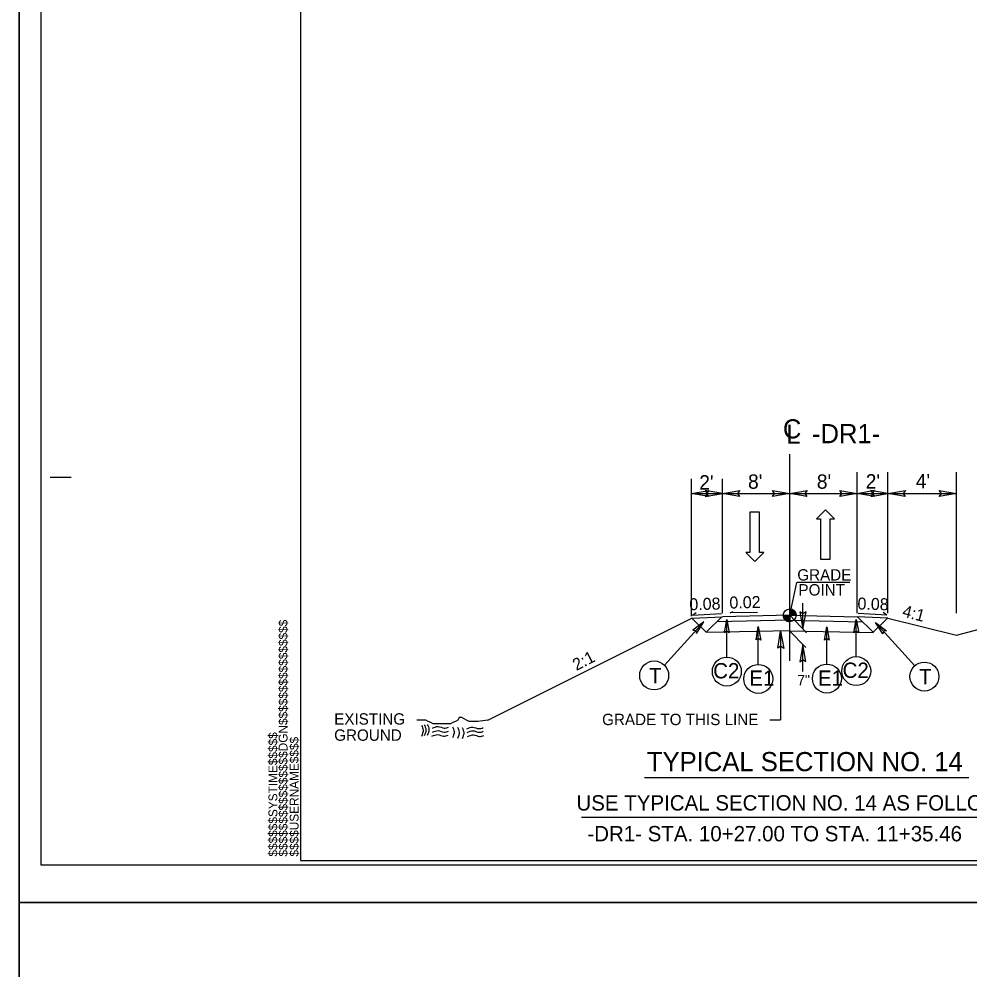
# Model space of a CAD drawing. Extents: x 573813 to 575363, y -54752 to -53123.
# Drawn here: x 574669.7 to 574782.7, y -54231.4 to -54118.5 of the extents above; entities that cross this region are included whole.
import ezdxf

# ---------------------------------------------------------------- set-up
doc = ezdxf.new("R2010")
doc.units = 0
for name, color, linetype in [('Old_Level_1', 7, 'Continuous'), ('Old_Level_11', 7, 'Continuous'), ('Old_Level_2', 7, 'Continuous'), ('Old_Level_3', 7, 'Continuous'), ('Prop Lane Arrow CELL', 7, 'Continuous'), ('Prop Pavement Schedule Description CELL', 7, 'Continuous'), ('Sheet Cutting Line CELL', 7, 'Continuous'), ('Sheet Plot Border Inside CELL', 7, 'Continuous'), ('Sheet Plot Border Outside CELL', 7, 'Continuous'), ('Sheet Typical CELL', 7, 'Continuous'), ('Typical Grade Point Symbol CELL', 7, 'Continuous'), ('Typical ID Circle CELL', 7, 'Continuous'), ('Typical Terminator CELL', 7, 'Continuous'), ('Typical Text ID Circle CELL', 7, 'Continuous'), ('Typical Text Label CELL', 7, 'Continuous')]:
    doc.layers.add(name, color=color, linetype=linetype)

msp = doc.modelspace()

# ---------------------------------------------------------------- linework, layer by layer
at = {"layer": 'Old_Level_1'}
for p, q in [((574781.07, -54191.67), (574799.55, -54186.73)), ((574749.71, -54189.27), (574750.16, -54188.98)), ((574754.17, -54189.02), (574754.54, -54188.83)), ((574757.43, -54188.95), (574754.17, -54189.02)), ((574772.81, -54189.27), (574772.36, -54188.98)), ((574725.4, -54201.75), (574749.64, -54189.63)), ((574749.64, -54189.63), (574753.26, -54189.46)), ((574749.64, -54189.63), (574751.34, -54191.32)), ((574749.71, -54189.27), (574753.14, -54189.1)), ((574753.2, -54189.46), (574751.34, -54191.32)), ((574761.26, -54189.89), (574752.59, -54190.07)), ((574761.26, -54189.3), (574753.26, -54189.46)), ((574761.26, -54189.3), (574769.26, -54189.46)), ((574761.26, -54189.89), (574769.93, -54190.07)), ((574772.93, -54189.63), (574769.26, -54189.46)), ((574769.32, -54189.46), (574771.17, -54191.32)), ((574772.81, -54189.27), (574769.38, -54189.1)), ((574772.87, -54189.63), (574771.18, -54191.32)), ((574772.93, -54189.63), (574781.07, -54191.67)), ((574761.28, -54191.15), (574751.33, -54191.33)), ((574761.24, -54191.15), (574771.19, -54191.33))]:
    msp.add_line(p, q, dxfattribs=at)
msp.add_lwpolyline([(574725.4, -54201.75), (574724.22, -54201.9), (574723.93, -54201.9), (574723.48, -54201.9), (574723.19, -54201.9), (574722.89, -54201.75), (574722.6, -54201.6), (574722.3, -54201.45), (574722.01, -54201.45), (574721.86, -54201.75), (574721.57, -54201.9), (574721.27, -54202.04), (574720.98, -54202.19), (574720.68, -54202.19), (574720.39, -54202.19), (574720.09, -54202.19), (574719.8, -54202.19), (574719.5, -54202.19), (574719.21, -54202.19), (574718.91, -54202.19), (574718.62, -54202.04), (574718.32, -54201.9), (574718.03, -54201.75), (574717.58, -54201.75), (574717.29, -54201.75), (574716.99, -54201.75)], dxfattribs=at)
at = {"layer": 'Old_Level_11'}
for p, q in [((574749.59, -54189.42), (574749.59, -54173.08)), ((574753.26, -54189.06), (574753.26, -54173.08)), ((574769.26, -54189.06), (574769.26, -54172.29)), ((574772.93, -54189.06), (574772.93, -54172.29)), ((574781.07, -54189.06), (574781.07, -54172.29)), ((574749.59, -54174.83), (574753.26, -54174.83)), ((574753.26, -54174.82), (574761.26, -54174.82)), ((574761.26, -54174.82), (574769.26, -54174.82)), ((574769.26, -54174.82), (574772.93, -54174.82)), ((574772.93, -54174.82), (574781.07, -54174.82)), ((574761.26, -54189.3), (574762.11, -54185.42)), ((574768.38, -54185.42), (574762.11, -54185.42)), ((574762.83, -54190.93), (574762.83, -54187.85)), ((574746.38, -54195.23), (574751.04, -54190.09)), ((574761.26, -54189.3), (574763.25, -54191.36)), ((574760.18, -54191.17), (574760.18, -54201.7)), ((574761.25, -54191.13), (574763.19, -54193.13)), ((574776.12, -54195.28), (574771.45, -54190.14)), ((574762.83, -54195.97), (574762.83, -54192.76)), ((574758.9, -54201.7), (574760.18, -54201.7)), ((574736.55, -54213.27), (574788.44, -54213.27))]:
    msp.add_line(p, q, dxfattribs=at)
for points in [[(574751.63, -54175.18), (574749.59, -54174.83), (574751.65, -54174.46), (574751.38, -54174.83)], [(574751.21, -54175.18), (574753.26, -54174.83), (574751.2, -54174.47), (574751.46, -54174.83)], [(574755.31, -54175.17), (574753.26, -54174.82), (574755.32, -54174.46), (574755.06, -54174.82)], [(574759.21, -54174.47), (574761.26, -54174.82), (574759.2, -54175.18), (574759.46, -54174.82)], [(574763.31, -54175.17), (574761.26, -54174.82), (574763.32, -54174.46), (574763.06, -54174.82)], [(574767.21, -54174.47), (574769.26, -54174.82), (574767.2, -54175.18), (574767.46, -54174.82)], [(574771.31, -54175.17), (574769.26, -54174.82), (574771.32, -54174.45), (574771.06, -54174.82)], [(574770.88, -54175.17), (574772.93, -54174.82), (574770.87, -54174.46), (574771.13, -54174.82)], [(574774.98, -54175.17), (574772.93, -54174.82), (574774.99, -54174.46), (574774.73, -54174.82)], [(574779.02, -54174.47), (574781.07, -54174.82), (574779.01, -54175.18), (574779.27, -54174.82)], [(574762.48, -54188.88), (574762.83, -54190.93), (574763.2, -54188.87), (574762.83, -54189.13)], [(574759.83, -54193.22), (574760.18, -54191.17), (574760.55, -54193.23), (574760.18, -54192.97)], [(574763.18, -54194.8), (574762.83, -54192.76), (574762.46, -54194.81), (574762.83, -54194.55)]]:
    msp.add_lwpolyline(points, close=True, dxfattribs=at)
at = {"layer": 'Old_Level_2'}
msp.add_line((574761.26, -54194.72), (574761.26, -54170.16), dxfattribs=at)
for points in [[(574717.53, -54202.37), (574717.72, -54202.93), (574717.52, -54203.68)], [(574717.53, -54202.37), (574717.72, -54202.93), (574717.52, -54203.68)], [(574717.86, -54202.3), (574718.05, -54202.87), (574717.85, -54203.62)], [(574717.86, -54202.3), (574718.05, -54202.87), (574717.85, -54203.62)], [(574718.22, -54202.26), (574718.41, -54202.83), (574718.2, -54203.58)], [(574718.22, -54202.26), (574718.41, -54202.83), (574718.2, -54203.58)], [(574718.82, -54202.71), (574719.5, -54202.51), (574720.23, -54202.69), (574720.75, -54202.58)], [(574718.82, -54202.71), (574719.5, -54202.51), (574720.23, -54202.69), (574720.75, -54202.58)], [(574718.77, -54203.66), (574719.45, -54203.47), (574720.17, -54203.65), (574720.7, -54203.53)], [(574718.77, -54203.66), (574719.45, -54203.47), (574720.17, -54203.65), (574720.7, -54203.53)], [(574718.82, -54203.18), (574719.5, -54202.99), (574720.22, -54203.17), (574720.74, -54203.05)], [(574718.82, -54203.18), (574719.5, -54202.99), (574720.22, -54203.17), (574720.74, -54203.05)], [(574721.21, -54202.54), (574721.4, -54203.11), (574721.2, -54203.86)], [(574721.21, -54202.54), (574721.4, -54203.11), (574721.2, -54203.86)], [(574721.81, -54202.59), (574722, -54203.16), (574721.8, -54203.91)], [(574721.81, -54202.59), (574722, -54203.16), (574721.8, -54203.91)], [(574722.36, -54202.64), (574722.55, -54203.21), (574722.35, -54203.95)], [(574722.36, -54202.64), (574722.55, -54203.21), (574722.35, -54203.95)], [(574722.93, -54202.77), (574723.61, -54202.57), (574724.33, -54202.76), (574724.86, -54202.64)], [(574722.93, -54202.77), (574723.61, -54202.57), (574724.33, -54202.76), (574724.86, -54202.64)], [(574722.95, -54203.2), (574723.63, -54203), (574724.35, -54203.19), (574724.87, -54203.07)], [(574722.95, -54203.2), (574723.63, -54203), (574724.35, -54203.19), (574724.87, -54203.07)], [(574723.01, -54203.7), (574723.7, -54203.5), (574724.42, -54203.68), (574724.94, -54203.57)], [(574723.01, -54203.7), (574723.7, -54203.5), (574724.42, -54203.68), (574724.94, -54203.57)]]:
    msp.add_spline(points, degree=3, dxfattribs=at)
at = {"layer": 'Prop Lane Arrow CELL'}
for p, q in [((574756.54, -54177.05), (574756.54, -54181.82)), ((574757.66, -54177.05), (574756.54, -54177.05)), ((574757.66, -54181.82), (574757.66, -54177.05)), ((574765.51, -54176.78), (574764.42, -54177.85)), ((574766.56, -54177.85), (574765.51, -54176.78)), ((574764.42, -54177.85), (574764.93, -54177.85)), ((574764.93, -54177.85), (574764.93, -54182.63)), ((574766.05, -54182.63), (574766.05, -54177.85)), ((574766.05, -54177.85), (574766.56, -54177.85)), ((574756.54, -54181.82), (574756.03, -54181.82)), ((574756.03, -54181.82), (574757.12, -54182.9)), ((574757.12, -54182.9), (574758.17, -54181.82)), ((574758.17, -54181.82), (574757.66, -54181.82)), ((574764.93, -54182.63), (574766.05, -54182.63))]:
    msp.add_line(p, q, dxfattribs=at)
at = {"layer": 'Sheet Cutting Line CELL'}
for p, q in [((574669.73, -54223.42), (574669.73, -54003.31)), ((575006.71, -54223.42), (574669.73, -54223.42)), ((574669.73, -54443.54), (574669.73, -54223.42)), ((574669.73, -54223.42), (575006.71, -54223.42))]:
    msp.add_line(p, q, dxfattribs=at)
at = {"layer": 'Sheet Plot Border Inside CELL'}
msp.add_lwpolyline([(575005.81, -54007.8), (574672.33, -54007.8), (574672.33, -54218.93), (575005.81, -54218.93)], close=True, dxfattribs=at)
at = {"layer": 'Sheet Plot Border Outside CELL'}
for p, q in [((574669.73, -54003.31), (574669.73, -54223.42)), ((574669.73, -54223.42), (575006.71, -54223.42)), ((575006.71, -54223.42), (574669.73, -54223.42)), ((574669.73, -54223.42), (574669.73, -54443.54))]:
    msp.add_line(p, q, dxfattribs=at)
msp.add_lwpolyline([(575006.71, -54003.31), (574669.73, -54003.31), (574669.73, -54223.42), (575006.71, -54223.42)], close=True, dxfattribs=at)
at = {"layer": 'Sheet Typical CELL'}
for p, q in [((574673.43, -54172.9), (574675.93, -54172.9)), ((574703.15, -54218.42), (574703.15, -54218.42)), ((574703.15, -54218.42), (574703.15, -54218.42)), ((574703.15, -54218.42), (574703.15, -54218.42)), ((574703.15, -54218.42), (574703.15, -54218.42)), ((574703.15, -54218.42), (574703.15, -54218.42)), ((574703.15, -54218.42), (574703.15, -54218.42))]:
    msp.add_line(p, q, dxfattribs=at)
msp.add_lwpolyline([(575003.31, -54008.31), (574703.15, -54008.31), (574703.15, -54218.42), (575003.31, -54218.42)], close=True, dxfattribs=at)
msp.add_lwpolyline([(574710.65, -54218.42), (574710.65, -54218.42)], dxfattribs=at)
at = {"layer": 'Typical Grade Point Symbol CELL'}
for p, q in [((574761.26, -54189.3), (574761.26, -54188.53)), ((574760.5, -54189.3), (574761.26, -54189.3)), ((574762.02, -54189.3), (574761.26, -54189.3)), ((574761.26, -54190.06), (574761.26, -54189.3)), ((574761.26, -54189.3), (574761.26, -54190.06))]:
    msp.add_line(p, q, dxfattribs=at)
for points in [[(574761.27, -54188.53), (574761.27, -54188.53), (574761.27, -54189.3)], [(574761.28, -54188.53), (574761.28, -54189.3)], [(574761.3, -54188.53), (574761.3, -54189.3)], [(574761.31, -54188.53), (574761.31, -54189.3)], [(574761.33, -54188.54), (574761.33, -54189.3)], [(574761.34, -54188.54), (574761.34, -54189.3)], [(574761.36, -54188.54), (574761.36, -54189.3)], [(574761.37, -54188.54), (574761.37, -54189.3)], [(574761.39, -54188.54), (574761.39, -54189.3)], [(574761.4, -54188.55), (574761.4, -54189.3)], [(574761.42, -54188.55), (574761.42, -54189.3)], [(574761.43, -54188.55), (574761.43, -54189.3)], [(574761.45, -54188.56), (574761.45, -54189.3)], [(574761.46, -54188.56), (574761.46, -54189.3)], [(574761.48, -54188.56), (574761.48, -54189.3)], [(574761.49, -54188.57), (574761.49, -54189.3)], [(574761.51, -54188.57), (574761.51, -54189.3)], [(574761.53, -54188.58), (574761.53, -54189.3)], [(574761.54, -54188.59), (574761.54, -54189.3)], [(574761.56, -54188.59), (574761.56, -54189.3)], [(574761.57, -54188.6), (574761.57, -54189.3)], [(574761.59, -54188.61), (574761.59, -54189.3)], [(574761.6, -54188.61), (574761.6, -54189.3)], [(574761.62, -54188.62), (574761.62, -54189.3)], [(574761.63, -54188.63), (574761.63, -54189.3)], [(574761.65, -54188.64), (574761.65, -54189.3)], [(574761.66, -54188.65), (574761.66, -54189.3)], [(574761.68, -54188.66), (574761.68, -54189.3)], [(574761.69, -54188.67), (574761.69, -54189.3)], [(574761.71, -54188.68), (574761.71, -54189.3)], [(574761.72, -54188.69), (574761.72, -54189.3)], [(574761.74, -54188.7), (574761.74, -54189.3)], [(574761.75, -54188.72), (574761.75, -54189.3)], [(574761.77, -54188.73), (574761.77, -54189.3)], [(574761.78, -54188.74), (574761.78, -54189.3)], [(574761.8, -54188.76), (574761.8, -54189.3)], [(574761.82, -54188.77), (574761.82, -54189.3)], [(574761.83, -54188.79), (574761.83, -54189.3)], [(574761.85, -54188.81), (574761.85, -54189.3)], [(574761.86, -54188.83), (574761.86, -54189.3)], [(574761.88, -54188.85), (574761.88, -54189.3)], [(574761.89, -54188.87), (574761.89, -54189.3)], [(574761.91, -54188.89), (574761.91, -54189.3)], [(574761.92, -54188.92), (574761.92, -54189.3)], [(574761.94, -54188.95), (574761.94, -54189.3)], [(574761.95, -54188.98), (574761.95, -54189.3)], [(574760.5, -54189.3), (574760.5, -54189.38)], [(574760.51, -54189.3), (574760.51, -54189.47)], [(574760.53, -54189.3), (574760.53, -54189.52)], [(574760.54, -54189.3), (574760.54, -54189.57)], [(574760.56, -54189.3), (574760.56, -54189.6)], [(574760.58, -54189.3), (574760.58, -54189.64)], [(574760.59, -54189.3), (574760.59, -54189.67)], [(574760.61, -54189.3), (574760.61, -54189.69)], [(574760.62, -54189.3), (574760.62, -54189.72)], [(574760.64, -54189.3), (574760.64, -54189.74)], [(574760.65, -54189.3), (574760.65, -54189.76)], [(574760.67, -54189.3), (574760.67, -54189.78)], [(574760.68, -54189.3), (574760.68, -54189.8)], [(574760.7, -54189.3), (574760.7, -54189.81)], [(574760.71, -54189.3), (574760.71, -54189.83)], [(574760.73, -54189.3), (574760.73, -54189.85)], [(574760.74, -54189.3), (574760.74, -54189.86)], [(574760.76, -54189.3), (574760.76, -54189.87)], [(574760.77, -54189.3), (574760.77, -54189.89)], [(574760.79, -54189.3), (574760.79, -54189.9)], [(574760.8, -54189.3), (574760.8, -54189.91)], [(574760.82, -54189.3), (574760.82, -54189.92)], [(574760.83, -54189.3), (574760.83, -54189.93)], [(574760.85, -54189.3), (574760.85, -54189.94)], [(574760.87, -54189.3), (574760.87, -54189.95)], [(574760.88, -54189.3), (574760.88, -54189.96)], [(574760.9, -54189.3), (574760.9, -54189.97)], [(574760.91, -54189.3), (574760.91, -54189.98)], [(574760.93, -54189.3), (574760.93, -54189.98)], [(574760.94, -54189.3), (574760.94, -54189.99)], [(574760.96, -54189.3), (574760.96, -54190)], [(574760.97, -54189.3), (574760.97, -54190)], [(574760.99, -54189.3), (574760.99, -54190.01)], [(574761, -54189.3), (574761, -54190.01)], [(574761.02, -54189.3), (574761.02, -54190.02)], [(574761.03, -54189.3), (574761.03, -54190.03)], [(574761.05, -54189.3), (574761.05, -54190.03)], [(574761.06, -54189.3), (574761.06, -54190.03)], [(574761.08, -54189.3), (574761.08, -54190.04)], [(574761.09, -54189.3), (574761.09, -54190.04)], [(574761.11, -54189.3), (574761.11, -54190.04)], [(574761.13, -54189.3), (574761.13, -54190.05)], [(574761.14, -54189.3), (574761.14, -54190.05)], [(574761.16, -54189.3), (574761.16, -54190.05)], [(574761.17, -54189.3), (574761.17, -54190.05)], [(574761.19, -54189.3), (574761.19, -54190.06)], [(574761.2, -54189.3), (574761.2, -54190.06)], [(574761.22, -54189.3), (574761.22, -54190.06)], [(574761.23, -54189.3), (574761.23, -54190.06)], [(574761.25, -54189.3), (574761.25, -54190.06), (574761.25, -54190.06)], [(574761.97, -54189.01), (574761.97, -54189.3)], [(574761.98, -54189.06), (574761.98, -54189.3)], [(574762, -54189.11), (574762, -54189.3)], [(574762.01, -54189.19), (574762.01, -54189.3)]]:
    msp.add_lwpolyline(points, dxfattribs=at)
msp.add_circle((574761.26, -54189.3), 0.763, dxfattribs=at)
for start, end in [(359.9905, 89.9905), (179.9905, 269.9905)]:
    msp.add_arc((574761.26, -54189.3), 0.763, start, end, dxfattribs=at)
at = {"layer": 'Typical ID Circle CELL'}
for p, q in [((574753.79, -54194.26), (574753.79, -54189.78)), ((574769.16, -54194.2), (574769.16, -54189.78)), ((574757.53, -54195.13), (574757.53, -54190.64)), ((574765.67, -54195.09), (574765.67, -54190.67))]:
    msp.add_line(p, q, dxfattribs=at)
for centre in [(574753.79, -54195.98), (574769.16, -54195.92), (574745.16, -54196.44), (574757.53, -54196.85), (574765.67, -54196.81), (574777.25, -54196.57)]:
    msp.add_circle(centre, 1.72, dxfattribs=at)
at = {"layer": 'Typical Terminator CELL'}
for points in [[(574750.18, -54191.45), (574751.04, -54190.09), (574749.76, -54191.08), (574750.1, -54191.12)], [(574753.52, -54191.37), (574753.79, -54189.78), (574754.08, -54191.37), (574753.79, -54191.17)], [(574768.89, -54191.37), (574769.16, -54189.78), (574769.45, -54191.38), (574769.16, -54191.18)], [(574757.26, -54192.23), (574757.53, -54190.64), (574757.82, -54192.24), (574757.53, -54192.04)], [(574765.4, -54192.26), (574765.67, -54190.67), (574765.95, -54192.27), (574765.67, -54192.07)], [(574772.32, -54191.5), (574771.45, -54190.14), (574772.74, -54191.13), (574772.39, -54191.17)]]:
    msp.add_lwpolyline(points, close=True, dxfattribs=at)
at = {"layer": 'Typical Text Label CELL'}
msp.add_line((574744.03, -54208.54), (574782.55, -54208.54), dxfattribs=at)

# ---------------------------------------------------------------- texts
at = {"layer": 'Old_Level_1'}
for s, height, rotation, p in [('0.08', 1.421, 1.6633, (574749.36, -54188.71)), ('0.02', 1.421, 1.1919, (574754.11, -54188.5)), ('0.08', 1.421, 358.3367, (574769.29, -54188.6)), ('4:1', 1.421, 345.3432, (574774.54, -54189.42)), ('2:1', 1.421, 27.0855, (574735.92, -54195.92)), ('EXISTING', 1.35, 360, (574707.16, -54202.28)), ('GROUND', 1.35, 360, (574707.16, -54204.2)), ('USE TYPICAL SECTION NO. 14 AS FOLLOWS:', 1.8192, 360, (574735.93, -54212.48)), ('-DR1- STA. 10+27.00 TO STA. 11+35.46', 1.8192, 0, (574737.23, -54216.14))]:
    msp.add_text(s, height=height, rotation=rotation, dxfattribs=at).set_placement(p)
at = {"layer": 'Old_Level_11'}
for s, height, p in [("8'", 1.705, (574756.31, -54174.27)), ("8'", 1.705, (574764.48, -54174.27)), ("4'", 1.705, (574776.23, -54174.22)), ('GRADE TO THIS LINE', 1.3502, (574738.98, -54202.34))]:
    msp.add_text(s, height=height, rotation=360, dxfattribs=at).set_placement(p)
at = {"layer": 'Old_Level_2'}
for s, rotation, p in [('C', 360, (574760.45, -54168.29)), ('L', 359.9469, (574760.84, -54168.93))]:
    msp.add_text(s, height=2.27, rotation=rotation, dxfattribs=at).set_placement(p)
at = {"layer": 'Old_Level_3'}
for s, height, rotation, p in [('-DR1-', 2.274, 0, (574763.9, -54168.86)), ("2'", 1.705, 359.8329, (574750.51, -54174.36)), ("2'", 1.705, 359.8329, (574770.28, -54174.24)), ('GRADE', 1.35, 360, (574762.16, -54185.17)), ('POINT', 1.35, 360, (574762.3, -54186.95))]:
    msp.add_text(s, height=height, rotation=rotation, dxfattribs=at).set_placement(p)
at = {"layer": 'Prop Pavement Schedule Description CELL'}
msp.add_text('T', height=1.82, rotation=360, dxfattribs=at).set_placement((574744.56, -54197.37))
msp.add_text('T', height=1.82, dxfattribs=at).set_placement((574776.62, -54197.5))
at = {"layer": 'Sheet Typical CELL'}
for s, p in [('$$$$$$$$$$$$$$$$DGN$$$$$$$$$$$$$$$$', (574701.62, -54217.95)), ('$$$$$$SYSTIME$$$$$', (574700.41, -54217.95)), ('$$$$USERNAME$$$$', (574702.93, -54217.95))]:
    msp.add_text(s, height=1.0506, rotation=90, dxfattribs=at).set_placement(p)
at = {"layer": 'Typical Text ID Circle CELL'}
for s, height, p in [('C2', 1.819, (574752.17, -54196.79)), ('C2', 1.819, (574767.54, -54196.73)), ('E1', 1.819, (574756.46, -54197.67)), ('7"', 1.23, (574762.16, -54197.6)), ('E1', 1.819, (574764.61, -54197.67))]:
    msp.add_text(s, height=height, dxfattribs=at).set_placement(p)
at = {"layer": 'Typical Text Label CELL'}
msp.add_text('TYPICAL SECTION NO. 14', height=2.2739, dxfattribs=at).set_placement((574744.3, -54207.81))

doc.saveas('drawing.dxf')
